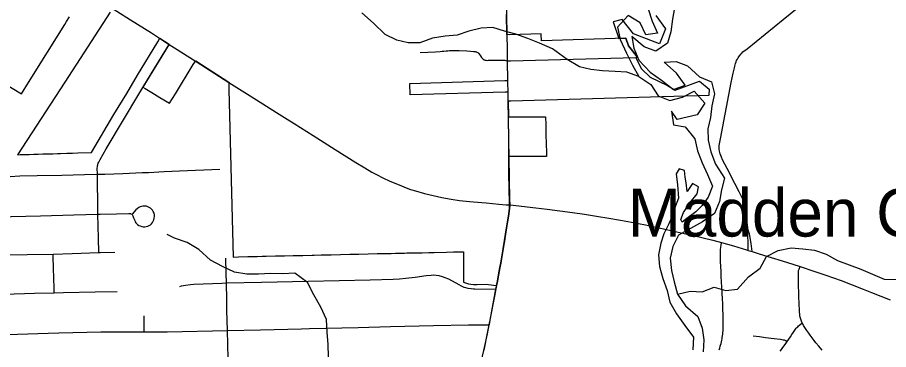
# Model space of a CAD drawing. Extents: x -6.4 to 34, y -4.2 to 22.
# Drawn here: x 3.551 to 4.993, y 16.282 to 16.831 of the extents above; entities that cross this region are included whole.
import ezdxf

# ---------------------------------------------------------------- set-up
doc = ezdxf.new("R2010")
doc.units = 0
for name, color, linetype in [('GM_X_City_Street', 7, 'Continuous'), ('GM_X_Corporation', 7, 'Continuous'), ('GM_X_County_Road', 7, 'Continuous'), ('GM_X_Major_River', 7, 'Continuous'), ('GM_X_Minor_River', 7, 'Continuous'), ('GM_X_Township_Road', 7, 'Continuous'), ('GM_X_Unincorporated_Text', 7, 'Continuous'), ('GM_X_US_Route', 7, 'Continuous')]:
    doc.layers.add(name, color=color, linetype=linetype)

msp = doc.modelspace()

# ---------------------------------------------------------------- linework, layer by layer
at = {"layer": 'GM_X_City_Street'}
for points in [[(4.7668, 16.4441), (4.7651, 16.4572), (4.7633, 16.4702), (4.7626, 16.4734), (4.7616, 16.4763), (4.7605, 16.4795), (4.7589, 16.4929), (4.757, 16.5133), (4.7566, 16.516), (4.7562, 16.5188), (4.7556, 16.5217), (4.7546, 16.5246), (4.7532, 16.5279), (4.7518, 16.5305), (4.7488, 16.5361), (4.7453, 16.5427), (4.7382, 16.5565), (4.7254, 16.5814), (4.7182, 16.5959), (4.7164, 16.6), (4.7152, 16.6028), (4.7143, 16.6055), (4.7136, 16.6077), (4.713, 16.6101), (4.7127, 16.6134), (4.7124, 16.6158), (4.7127, 16.6195), (4.7129, 16.6221), (4.7145, 16.6308), (4.7325, 16.7235), (4.7356, 16.7394), (4.7376, 16.7481), (4.7382, 16.751), (4.7389, 16.7532), (4.7394, 16.7552), (4.7404, 16.7577), (4.7413, 16.7599), (4.7426, 16.7622), (4.7437, 16.7644), (4.7449, 16.7663), (4.7461, 16.7681), (4.7486, 16.7711), (4.7501, 16.7725), (4.7517, 16.7742), (4.7585, 16.7797), (4.8182, 16.8279), (4.8644, 16.8659)], [(4.2176, 16.7736), (4.243, 16.7745), (4.2506, 16.775), (4.2542, 16.7753), (4.257, 16.7755), (4.261, 16.7759), (4.2636, 16.7761), (4.2665, 16.7764), (4.2701, 16.7765), (4.2739, 16.7767), (4.2778, 16.7766), (4.2822, 16.7766), (4.295, 16.7761), (4.3009, 16.7757), (4.3062, 16.7752), (4.3088, 16.7748), (4.3098, 16.7746), (4.3107, 16.7744), (4.3116, 16.774), (4.3132, 16.7731), (4.3139, 16.7726), (4.3146, 16.7719), (4.3161, 16.77), (4.3175, 16.7679), (4.3192, 16.7652), (4.3199, 16.7643), (4.3208, 16.7633), (4.3222, 16.7622), (4.3235, 16.7615), (4.3242, 16.7611), (4.3251, 16.7608), (4.327, 16.7605), (4.3289, 16.7604), (4.3309, 16.7605), (4.3523, 16.7609), (4.3564, 16.7608), (4.3581, 16.7606), (4.3596, 16.7603), (4.3623, 16.7595)], [(4.7606, 16.446), (4.7602, 16.4585), (4.7597, 16.4705), (4.7598, 16.4738), (4.7601, 16.4762), (4.7605, 16.4795)], [(4.7125, 16.2814), (4.7134, 16.2842), (4.7143, 16.2874), (4.7149, 16.2894), (4.7157, 16.2921), (4.7164, 16.295), (4.7168, 16.2973), (4.7172, 16.2996), (4.7176, 16.3019), (4.7181, 16.3045), (4.7185, 16.3073), (4.7187, 16.31), (4.719, 16.3128), (4.7191, 16.3153), (4.7192, 16.3184), (4.7192, 16.3214), (4.7193, 16.3259), (4.7192, 16.3298), (4.7192, 16.3344), (4.719, 16.3393), (4.7187, 16.3485), (4.7183, 16.3583), (4.7179, 16.3661), (4.717, 16.3854), (4.7165, 16.3941), (4.716, 16.403), (4.7156, 16.4105), (4.7152, 16.42), (4.7149, 16.4268), (4.7149, 16.4306), (4.7149, 16.4345), (4.7148, 16.4382), (4.7147, 16.4409), (4.7147, 16.443), (4.7147, 16.4451), (4.7149, 16.4478), (4.7151, 16.4501), (4.7153, 16.452), (4.7156, 16.4542), (4.7162, 16.4592)], [(4.8827, 16.2808), (4.8801, 16.284), (4.8772, 16.2876), (4.8726, 16.2933), (4.8697, 16.2971), (4.8662, 16.3016), (4.863, 16.3059), (4.8607, 16.3091), (4.8577, 16.3135), (4.8553, 16.3169), (4.8533, 16.32), (4.852, 16.322), (4.8506, 16.3243), (4.8497, 16.3259), (4.849, 16.3275), (4.8485, 16.3289), (4.8479, 16.3304), (4.8474, 16.3321), (4.8469, 16.3339), (4.8465, 16.3358), (4.8461, 16.3382), (4.8457, 16.3409), (4.8455, 16.344), (4.8453, 16.3473), (4.8451, 16.3505), (4.845, 16.3539), (4.8448, 16.358), (4.8445, 16.3691), (4.8438, 16.3946), (4.8437, 16.3998), (4.8435, 16.4048), (4.8435, 16.4076), (4.8435, 16.4097), (4.8436, 16.4106), (4.8437, 16.4114), (4.8439, 16.4125), (4.8448, 16.4152), (4.8463, 16.4195)], [(4.8136, 16.2794), (4.8157, 16.2823), (4.818, 16.2855), (4.8201, 16.2883), (4.8226, 16.2919), (4.8251, 16.2955), (4.8303, 16.3032), (4.8328, 16.3069), (4.8355, 16.3109), (4.8377, 16.3141), (4.8389, 16.3158), (4.84, 16.3171), (4.8411, 16.3183), (4.8425, 16.3197), (4.8439, 16.321), (4.8456, 16.3225), (4.8497, 16.3259)], [(4.7687, 16.3047), (4.7789, 16.3034), (4.7892, 16.302), (4.8035, 16.3002), (4.8137, 16.2989), (4.8183, 16.2983), (4.8199, 16.298), (4.8212, 16.2976), (4.8224, 16.2971), (4.8235, 16.2965), (4.8251, 16.2955)]]:
    msp.add_lwpolyline(points, dxfattribs=at)
at = {"layer": 'GM_X_Corporation'}
for points in [[(3.705, 16.84), (3.6297, 16.7243), (3.5516, 16.6042), (3.5559, 16.6044), (3.5634, 16.6046), (3.5709, 16.6048), (3.5784, 16.6051), (3.5859, 16.6053), (3.5934, 16.6055), (3.6005, 16.6058), (3.6052, 16.6059), (3.61, 16.606), (3.618, 16.6063), (3.6226, 16.6064), (3.6333, 16.6068), (3.6351, 16.6068), (3.6385, 16.6069), (3.6424, 16.607), (3.6515, 16.6073), (3.6742, 16.6078), (3.7111, 16.6709), (3.7323, 16.7058), (3.7504, 16.7357), (3.7836, 16.7909), (3.7872, 16.7968), (3.8027, 16.7874), (3.7592, 16.7159), (3.7629, 16.7138), (3.774, 16.7071), (3.7871, 16.6991), (3.8032, 16.6893), (3.8129, 16.7051), (3.8424, 16.7537), (3.8464, 16.7597), (3.9012, 16.7245), (3.9012, 16.7165), (3.9013, 16.7119), (3.9086, 16.435), (3.917, 16.4352), (3.9328, 16.4357), (3.9479, 16.4361), (3.9562, 16.4363), (3.9631, 16.4365), (3.9782, 16.4368), (3.9934, 16.4372), (4.0078, 16.4375), (4.0085, 16.4375), (4.0106, 16.4375), (4.0237, 16.4378), (4.0389, 16.4382), (4.0416, 16.4382), (4.0423, 16.4382), (4.054, 16.4385), (4.0692, 16.4388), (4.0707, 16.4389), (4.0862, 16.4392), (4.1014, 16.4396), (4.1032, 16.4396), (4.1138, 16.4398), (4.1165, 16.4399), (4.1317, 16.4402), (4.1465, 16.4406), (4.1617, 16.4409), (4.1699, 16.4411), (4.1768, 16.4412), (4.192, 16.4416), (4.1955, 16.4417), (4.2057, 16.4419), (4.221, 16.4422), (4.2322, 16.4425), (4.2408, 16.4427), (4.2615, 16.4431), (4.2729, 16.4434), (4.2829, 16.4436), (4.2891, 16.4438), (4.2893, 16.4438), (4.2893, 16.4348), (4.2893, 16.3985), (4.2893, 16.3936), (4.2925, 16.3922), (4.2977, 16.3907), (4.3015, 16.39), (4.3058, 16.3895), (4.3122, 16.3896), (4.3268, 16.3899), (4.3392, 16.3886), (4.3441, 16.3879), (4.3455, 16.395), (4.3475, 16.4054), (4.3498, 16.4178), (4.3513, 16.4255), (4.3551, 16.4484), (4.3574, 16.4621), (4.3605, 16.4832), (4.3621, 16.4932), (4.3637, 16.5028), (4.3656, 16.5154), (4.3655, 16.5246), (4.3647, 16.5727), (4.3645, 16.6011), (4.3644, 16.628), (4.3639, 16.6672), (4.3634, 16.6929), (4.3631, 16.7079), (4.3583, 16.708), (4.2012, 16.7033), (4.2008, 16.7223), (4.358, 16.7269), (4.3628, 16.727), (4.3621, 16.7596), (4.367, 16.7596), (4.5744, 16.7653), (4.5773, 16.7654), (4.5623, 16.7845), (4.5582, 16.7968), (4.4184, 16.7929), (4.4181, 16.8033), (4.4181, 16.8043), (4.3661, 16.8028), (4.3614, 16.803), (4.3608, 16.836)], [(4.6077, 16.8348), (4.6239, 16.8125), (4.6137, 16.7878), (4.5706, 16.8043), (4.5518, 16.8279), (4.5368, 16.8242), (4.5467, 16.7965), (4.5467, 16.7965), (4.5582, 16.7968), (4.5623, 16.7845), (4.5773, 16.7654), (4.5744, 16.7653), (4.5832, 16.7469), (4.5839, 16.7464), (4.5983, 16.7325), (4.627, 16.719), (4.6399, 16.7108), (4.6799, 16.726), (4.6961, 16.7129), (4.6951, 16.7021), (4.368, 16.693), (4.3634, 16.6929), (4.3639, 16.6672), (4.3684, 16.6671), (4.4253, 16.667), (4.4255, 16.6537), (4.4256, 16.6471), (4.4256, 16.6405), (4.4259, 16.6311), (4.426, 16.6289), (4.4265, 16.6014), (4.3751, 16.6015), (4.3714, 16.6015), (4.3645, 16.6011), (4.3647, 16.5727), (4.3655, 16.5246), (4.3656, 16.5154), (4.3637, 16.5028), (4.3621, 16.4932), (4.3605, 16.4832), (4.3574, 16.4621), (4.3551, 16.4484), (4.3513, 16.4255), (4.3498, 16.4178), (4.3475, 16.4054), (4.3455, 16.395), (4.3441, 16.3879), (4.343, 16.3825), (4.3407, 16.3701), (4.3337, 16.3337), (4.3317, 16.3232), (4.3317, 16.3231), (4.3316, 16.3229), (4.3288, 16.3088), (4.3229, 16.2809)], [(3.5085, 16.7347), (3.5583, 16.7051), (3.5698, 16.7236), (3.6298, 16.8197), (3.6328, 16.8246), (3.6378, 16.8326)]]:
    msp.add_lwpolyline(points, dxfattribs=at)
at = {"layer": 'GM_X_County_Road'}
for p, q in [((4.363, 16.7255), (4.3623, 16.7595)), ((4.3632, 16.7068), (4.363, 16.7255)), ((4.3641, 16.666), (4.3636, 16.6903))]:
    msp.add_line(p, q, dxfattribs=at)
for points in [[(4.3616, 16.8019), (4.361, 16.8354), (4.3605, 16.8564)], [(4.3623, 16.7595), (4.362, 16.7792), (4.3616, 16.8019)], [(4.3636, 16.6903), (4.3636, 16.6912), (4.3632, 16.7068)], [(4.3652, 16.6008), (4.3646, 16.6275), (4.3641, 16.666)], [(4.3666, 16.5211), (4.3662, 16.5307), (4.3657, 16.5644), (4.3652, 16.6008)], [(4.3432, 16.3819), (4.3457, 16.3945), (4.3477, 16.4049), (4.35, 16.4173), (4.3515, 16.4249), (4.3553, 16.4479), (4.3576, 16.4615), (4.3607, 16.4827), (4.3623, 16.4926), (4.3639, 16.5022), (4.3663, 16.515), (4.3666, 16.5211)], [(4.2711, 16.0253), (4.2753, 16.0456), (4.2782, 16.0596), (4.2786, 16.062), (4.2806, 16.0719), (4.2817, 16.0768), (4.2858, 16.0971), (4.291, 16.1225), (4.2943, 16.1389), (4.2945, 16.1397), (4.3011, 16.1718), (4.3068, 16.199), (4.3072, 16.201), (4.3115, 16.2231), (4.3158, 16.2449), (4.3168, 16.2498), (4.3211, 16.2708), (4.3231, 16.2803), (4.329, 16.3082), (4.3319, 16.3228), (4.3339, 16.3331), (4.3409, 16.3696), (4.3432, 16.3819)]]:
    msp.add_lwpolyline(points, dxfattribs=at)
at = {"layer": 'GM_X_Major_River'}
for points in [[(4.5947, 16.8454), (4.6016, 16.825), (4.6103, 16.8055), (4.5911, 16.8028), (4.582, 16.8227), (4.562, 16.8344), (4.5442, 16.8151), (4.5484, 16.795), (4.5591, 16.7721), (4.569, 16.7526), (4.5793, 16.7334), (4.5992, 16.7206), (4.6114, 16.7015), (4.6309, 16.6939), (4.652, 16.6993), (4.6711, 16.7092), (4.6885, 16.6898), (4.676, 16.6702), (4.6427, 16.6625), (4.6337, 16.6764), (4.637, 16.6538), (4.6564, 16.6504), (4.6723, 16.6303), (4.6765, 16.6106), (4.6841, 16.591), (4.6929, 16.5715), (4.7012, 16.5523)], [(4.6386, 16.8475), (4.6353, 16.8284), (4.6326, 16.8078), (4.627, 16.7887), (4.6076, 16.7754), (4.5885, 16.783), (4.568, 16.7996), (4.5715, 16.7803), (4.5798, 16.7608), (4.598, 16.741), (4.6173, 16.7278)], [(4.6173, 16.7278), (4.6369, 16.7119), (4.6561, 16.7195), (4.642, 16.739), (4.6216, 16.7571), (4.6413, 16.7583), (4.6603, 16.7511), (4.6797, 16.7333), (4.6995, 16.7246), (4.7045, 16.705), (4.7004, 16.6851), (4.6981, 16.6661), (4.6936, 16.647), (4.694, 16.6281), (4.6989, 16.6088), (4.7062, 16.5888), (4.7214, 16.5653), (4.7165, 16.5462), (4.7131, 16.5271), (4.7048, 16.5072), (4.6847, 16.4935), (4.6652, 16.4821), (4.6453, 16.4714), (4.6355, 16.4522), (4.6314, 16.4331), (4.6333, 16.413), (4.6379, 16.3938), (4.6436, 16.3734), (4.6565, 16.3543), (4.6769, 16.3365), (4.6845, 16.3173), (4.6868, 16.298), (4.6861, 16.2783)], [(4.7012, 16.5523), (4.694, 16.5343), (4.6845, 16.5201), (4.6737, 16.5096), (4.6592, 16.499), (4.6513, 16.4928), (4.649, 16.4973), (4.6536, 16.5088), (4.6647, 16.5253), (4.6761, 16.5396), (4.6781, 16.551), (4.6682, 16.5569), (4.6627, 16.5484), (4.6594, 16.5434), (4.6579, 16.5578), (4.6562, 16.5673), (4.6549, 16.5783), (4.6461, 16.5811), (4.6413, 16.5727), (4.6436, 16.5545), (4.6452, 16.5325), (4.6387, 16.5153), (4.6363, 16.5057), (4.629, 16.49), (4.621, 16.4735), (4.6161, 16.4579)], [(4.6161, 16.4579), (4.6123, 16.4384), (4.6138, 16.4191), (4.6192, 16.3995), (4.6264, 16.3799), (4.6306, 16.3606), (4.642, 16.3411), (4.6556, 16.3217), (4.6701, 16.3022), (4.669, 16.2813)]]:
    msp.add_lwpolyline(points, dxfattribs=at)
at = {"layer": 'GM_X_Minor_River'}
for points in [[(4.5793, 16.7334), (4.5598, 16.741), (4.5404, 16.7421), (4.5192, 16.7428), (4.5002, 16.7454), (4.4812, 16.7496), (4.4608, 16.762), (4.4366, 16.7797), (4.4152, 16.7888), (4.3961, 16.7963), (4.3763, 16.8035), (4.3572, 16.8088), (4.3381, 16.8148), (4.3185, 16.8137), (4.2985, 16.8087), (4.2789, 16.8018), (4.2589, 16.8006), (4.2381, 16.7971), (4.2174, 16.7895), (4.1981, 16.7895), (4.1791, 16.7936), (4.1596, 16.8031), (4.1406, 16.822), (4.1213, 16.8391)], [(4.0661, 16.27), (4.0653, 16.2905), (4.0637, 16.3109), (4.0626, 16.3318), (4.0534, 16.3521), (4.042, 16.3723), (4.0314, 16.393), (4.0102, 16.4081), (3.9901, 16.4073), (3.9704, 16.4076), (3.9504, 16.4064), (3.9311, 16.4064), (3.9105, 16.4098), (3.891, 16.4192), (3.8711, 16.4298), (3.8518, 16.4472), (3.8322, 16.4593), (3.8116, 16.4661), (3.7994, 16.4723)], [(4.6436, 16.3734), (4.6643, 16.3788), (4.6844, 16.3777), (4.7039, 16.3853), (4.7234, 16.3797), (4.7427, 16.3816), (4.7612, 16.4025), (4.7802, 16.4166), (4.7908, 16.4361), (4.8099, 16.4457), (4.8314, 16.4503), (4.8508, 16.4488), (4.8701, 16.4462), (4.8892, 16.4398), (4.9084, 16.4295), (4.9275, 16.422), (4.9469, 16.4152), (4.966, 16.4065), (4.9855, 16.3982), (5.0064, 16.3979), (5.0265, 16.3968), (5.0386, 16.396), (5.0455, 16.397)]]:
    msp.add_lwpolyline(points, dxfattribs=at)
at = {"layer": 'GM_X_Township_Road'}
msp.add_line((3.7614, 16.311), (3.7613, 16.3376), dxfattribs=at)
for points in [[(3.759, 16.7155), (3.7907, 16.7681), (3.8024, 16.7868)], [(3.6861, 16.4424), (3.6856, 16.4664), (3.6847, 16.5057), (3.6843, 16.5266), (3.684, 16.5563), (3.6838, 16.5719), (3.6836, 16.582), (3.6838, 16.5842), (3.684, 16.5856), (3.6844, 16.5874), (3.6846, 16.5885), (3.6852, 16.5901), (3.6859, 16.5919), (3.687, 16.594), (3.6881, 16.5962), (3.6984, 16.614), (3.754, 16.707), (3.759, 16.7155)], [(3.4225, 16.5653), (3.4654, 16.5664), (3.4935, 16.5672), (3.5266, 16.5681), (3.5395, 16.5684), (3.5557, 16.5691), (3.5841, 16.5699), (3.6252, 16.5704), (3.6625, 16.5714), (3.6838, 16.5719), (3.696, 16.5722), (3.7256, 16.5732), (3.7581, 16.5747)], [(3.7581, 16.5747), (3.7682, 16.5751), (3.794, 16.5764), (3.8196, 16.5777), (3.8863, 16.5801)], [(3.7152, 16.5064), (3.736, 16.5069), (3.7374, 16.5069), (3.7385, 16.5068), (3.7391, 16.5066), (3.7407, 16.5058), (3.7412, 16.5054), (3.742, 16.5043), (3.7424, 16.5033), (3.7437, 16.4998), (3.7455, 16.4952), (3.7464, 16.4935), (3.7476, 16.4915), (3.7483, 16.4906), (3.75, 16.4888), (3.7521, 16.4874), (3.7543, 16.4864), (3.7573, 16.4855), (3.7597, 16.4851), (3.7622, 16.485), (3.7647, 16.4854), (3.7671, 16.4861), (3.7693, 16.4871), (3.7714, 16.4884), (3.7733, 16.4901), (3.7749, 16.492), (3.7762, 16.4941), (3.7771, 16.4964), (3.7779, 16.4994), (3.7782, 16.5025), (3.7781, 16.505), (3.7775, 16.5074), (3.7763, 16.5102), (3.775, 16.5124), (3.7734, 16.5143), (3.7715, 16.5159), (3.7694, 16.5172), (3.7672, 16.5183), (3.7648, 16.5189), (3.7617, 16.5193), (3.7606, 16.5193), (3.7592, 16.5192), (3.7568, 16.5188), (3.7544, 16.518), (3.7522, 16.5168), (3.7497, 16.515), (3.7475, 16.5129), (3.7411, 16.506)], [(3.0231, 16.4898), (3.0371, 16.4901), (3.0842, 16.4909), (3.1562, 16.4926), (3.1927, 16.4934), (3.2334, 16.4944), (3.2947, 16.496), (3.3884, 16.4981), (3.3922, 16.4982), (3.4483, 16.4997), (3.4918, 16.5008), (3.5895, 16.5034), (3.6446, 16.5049), (3.6847, 16.5057)], [(3.6847, 16.5057), (3.6884, 16.5058), (3.7152, 16.5064)], [(3.0689, 16.4266), (3.0774, 16.4269), (3.0987, 16.4276), (3.1732, 16.4296), (3.2153, 16.431), (3.2327, 16.4316), (3.2347, 16.4317), (3.3082, 16.4338), (3.3436, 16.4348), (3.3771, 16.4364), (3.3914, 16.4369), (3.3939, 16.4369), (3.4075, 16.437), (3.4808, 16.4382), (3.6104, 16.4399), (3.642, 16.441), (3.6861, 16.4424), (3.6885, 16.4425), (3.7124, 16.4429)], [(3.6124, 16.376), (3.6122, 16.3833), (3.6111, 16.4168), (3.6105, 16.4358), (3.6104, 16.4399)], [(3.9066, 15.9871), (3.9064, 16.0085), (3.9059, 16.044), (3.9055, 16.0855), (3.9053, 16.0923), (3.9047, 16.1104), (3.9044, 16.1202), (3.903, 16.1587), (3.901, 16.2204), (3.9008, 16.2386), (3.9001, 16.2669), (3.8989, 16.3134), (3.898, 16.347), (3.8977, 16.3644), (3.8972, 16.3921), (3.8969, 16.4085), (3.8965, 16.4331)], [(3.8972, 16.3921), (3.9555, 16.3934), (4.0326, 16.3952), (4.135, 16.3975), (4.1729, 16.3983), (4.1834, 16.3988), (4.1939, 16.3998), (4.2093, 16.4017), (4.2278, 16.4042), (4.2358, 16.4052), (4.2402, 16.4055), (4.2441, 16.4052), (4.2485, 16.4045), (4.2539, 16.403), (4.2587, 16.4013), (4.2644, 16.3987), (4.2815, 16.3898), (4.2856, 16.3876), (4.2879, 16.3862), (4.2899, 16.3854), (4.2926, 16.3847), (4.2968, 16.3837), (4.3022, 16.383), (4.3058, 16.3826), (4.3084, 16.3826), (4.3432, 16.3819)], [(3.8199, 16.3864), (3.8228, 16.3872), (3.8294, 16.3885), (3.8377, 16.3895), (3.8432, 16.3899), (3.8899, 16.3918), (3.8972, 16.3921)], [(3.3951, 16.3717), (3.404, 16.3719), (3.5294, 16.3738), (3.5797, 16.3751), (3.6124, 16.376), (3.6275, 16.3765), (3.6803, 16.3776), (3.7165, 16.378)], [(3.3965, 16.3042), (3.4017, 16.3043), (3.455, 16.3054), (3.5176, 16.3064), (3.6026, 16.3089), (3.6199, 16.3094), (3.6894, 16.3111), (3.7058, 16.3113), (3.736, 16.3113), (3.7614, 16.311), (3.7993, 16.3114), (3.8989, 16.3134), (3.9538, 16.3146), (4.0216, 16.3163), (4.0347, 16.3167), (4.1153, 16.3186), (4.1687, 16.3199), (4.24, 16.322), (4.2978, 16.3227), (4.3243, 16.3228), (4.3319, 16.3228)]]:
    msp.add_lwpolyline(points, dxfattribs=at)
at = {"layer": 'GM_X_US_Route'}
for p, q in [((3.7883, 16.7958), (3.8024, 16.7868)), ((3.8471, 16.7585), (3.9014, 16.724))]:
    msp.add_line(p, q, dxfattribs=at)
for points in [[(3.71, 16.8454), (3.7159, 16.8416), (3.7388, 16.8275), (3.7732, 16.8058), (3.7883, 16.7958)], [(3.8024, 16.7868), (3.8114, 16.7811), (3.8471, 16.7585)], [(3.9014, 16.724), (3.9366, 16.7018), (3.9635, 16.6848), (3.9803, 16.674), (3.998, 16.663), (4.0093, 16.6558), (4.0408, 16.6359), (4.0772, 16.6128), (4.1112, 16.5913), (4.126, 16.5825), (4.1377, 16.5756), (4.1453, 16.5715), (4.1562, 16.5658), (4.1678, 16.5606), (4.1828, 16.5542), (4.1947, 16.5493), (4.202, 16.547), (4.21, 16.5445), (4.2248, 16.5401), (4.2391, 16.5367), (4.2537, 16.5334), (4.2688, 16.5306), (4.2826, 16.5286), (4.2996, 16.5269), (4.3199, 16.5251), (4.3268, 16.5246), (4.3477, 16.5226), (4.3601, 16.5216), (4.3666, 16.5211)], [(4.3666, 16.5211), (4.409, 16.5163), (4.4278, 16.514), (4.4491, 16.5115), (4.4699, 16.5086), (4.4898, 16.5057), (4.5094, 16.5026), (4.5298, 16.4993), (4.5493, 16.4958), (4.5672, 16.4926), (4.5904, 16.4881), (4.6203, 16.4819), (4.6445, 16.4764), (4.6701, 16.4707), (4.6858, 16.4669), (4.7021, 16.4627), (4.7162, 16.4592), (4.7359, 16.4536), (4.7579, 16.4468), (4.7606, 16.446), (4.7668, 16.4441), (4.7787, 16.4404), (4.7984, 16.4345), (4.8168, 16.4289), (4.8342, 16.4234), (4.8463, 16.4195), (4.8689, 16.4119), (4.889, 16.4048), (4.9141, 16.396), (4.9322, 16.3891), (4.9509, 16.3817), (4.9646, 16.3763), (4.9953, 16.364)]]:
    msp.add_lwpolyline(points, dxfattribs=at)

# ---------------------------------------------------------------- texts
at = {"layer": 'GM_X_Unincorporated_Text'}
msp.add_text('Madden Corners', height=0.078977, rotation=0, dxfattribs=at).set_placement((4.5612, 16.4689))

doc.saveas('drawing.dxf')
